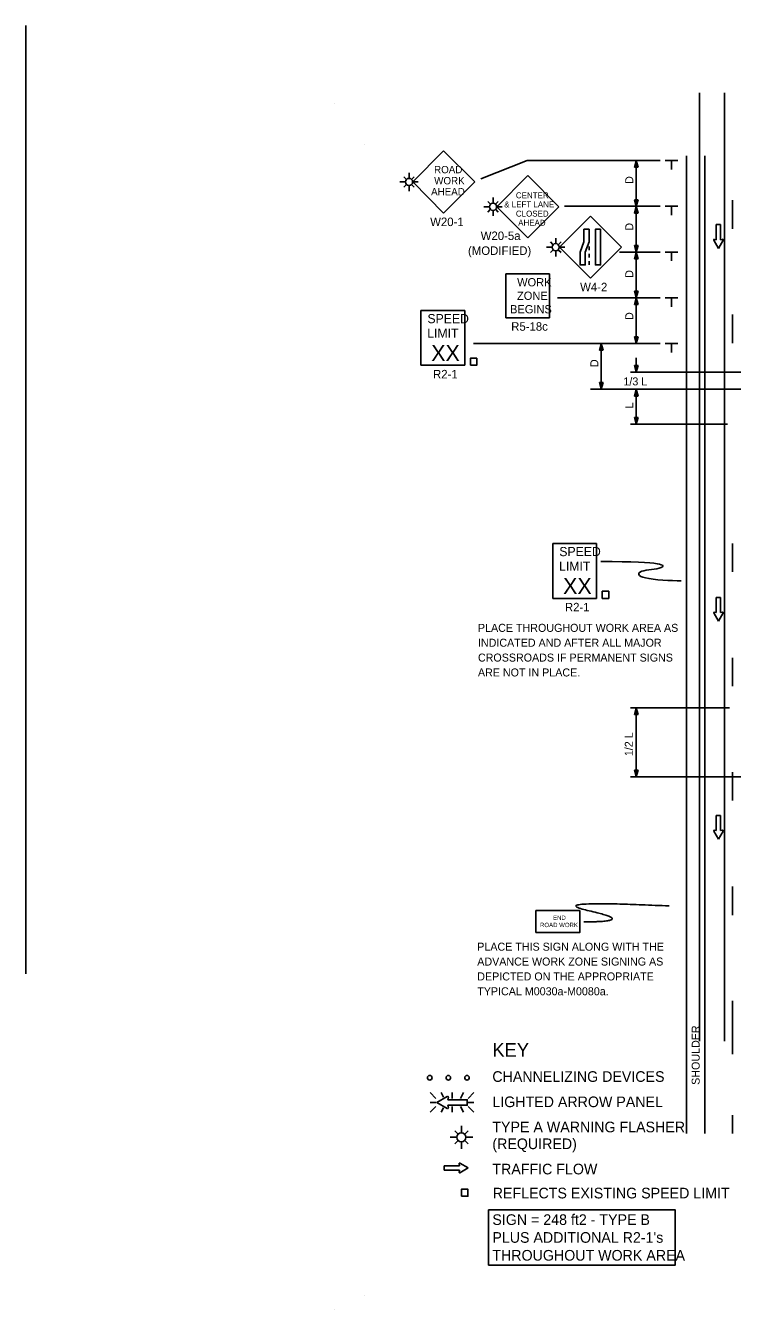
# Model space of a CAD drawing. Extents: x 16399 to 18476, y 7023 to 8321.
# Drawn here: x 16399 to 17017, y 7199 to 8321 of the extents above; entities that cross this region are included whole.
import ezdxf

# ---------------------------------------------------------------- set-up
doc = ezdxf.new("R2010")
doc.units = 0
for name, color, linetype in [('ALI_LEGAL_EX', 7, 'Continuous'), ('BORDER', 7, 'Continuous'), ('MT_SCRATCH_LEVEL_E', 7, 'Continuous'), ('PAVT_EDGE_EX', 7, 'Continuous'), ('TRAFFIC_SIGNS_PR', 7, 'Continuous'), ('TYPICAL_TEXT_DIMEN_EX', 7, 'Continuous'), ('TYPICAL_TEXT_DIMEN_PR', 7, 'Continuous')]:
    doc.layers.add(name, color=color, linetype=linetype)

msp = doc.modelspace()

# ---------------------------------------------------------------- linework, layer by layer
at = {"layer": 'ALI_LEGAL_EX'}
for points in [[(17017.1, 8168.5), (17017.1, 8143.5)], [(17017.1, 8068.5), (17017.1, 8043.5)], [(17017.1, 7868.5), (17017.1, 7843.5)], [(17017.1, 7768.5), (17017.1, 7743.5)], [(17017.1, 7668.5), (17017.1, 7643.5)], [(17017.1, 7568.5), (17017.1, 7543.5)], [(17017.1, 7468.5), (17017.1, 7443.5)], [(17017.1, 7368.5), (17017.1, 7352.5)]]:
    msp.add_lwpolyline(points, dxfattribs=at)
at = {"layer": 'BORDER'}
for p, q in [((16669.3, 8252.7), (16669.3, 8252.7)), ((16695.5, 8217), (16695.5, 8217)), ((16695.5, 7210.7), (16695.5, 7210.7)), ((16669.3, 7198.7), (16669.3, 7198.7))]:
    msp.add_line(p, q, dxfattribs=at)
at = {"layer": 'MT_SCRATCH_LEVEL_E'}
for p, q in [((17006.8, 8147.3), (17003, 8147.3)), ((17003, 8147.3), (17003, 8134)), ((17006.8, 8147.3), (17003, 8147.3)), ((17003, 8147.3), (17003, 8134)), ((17006.8, 8134), (17006.8, 8147.3)), ((17006.8, 8134), (17006.8, 8147.3)), ((17000.8, 8133.6), (17004.9, 8126.4)), ((17000.8, 8133.6), (17004.9, 8126.4)), ((17003, 8134), (17001.2, 8134.3)), ((17003, 8134), (17001.2, 8134.3)), ((17004.9, 8126.4), (17009, 8133.6)), ((17004.9, 8126.4), (17009, 8133.6)), ((17008.5, 8134.3), (17006.8, 8134)), ((17008.5, 8134.3), (17006.8, 8134)), ((17006.8, 7821.2), (17003, 7821.2)), ((17003, 7821.2), (17003, 7807.9)), ((17006.8, 7821.2), (17003, 7821.2)), ((17003, 7821.2), (17003, 7807.9)), ((17006.8, 7807.9), (17006.8, 7821.2)), ((17006.8, 7807.9), (17006.8, 7821.2)), ((17000.8, 7807.6), (17004.9, 7800.3)), ((17000.8, 7807.6), (17004.9, 7800.3)), ((17003, 7807.9), (17001.2, 7808.2)), ((17003, 7807.9), (17001.2, 7808.2)), ((17004.9, 7800.3), (17009, 7807.6)), ((17004.9, 7800.3), (17009, 7807.6)), ((17008.5, 7808.2), (17006.8, 7807.9)), ((17008.5, 7808.2), (17006.8, 7807.9)), ((17006.8, 7630.6), (17003, 7630.6)), ((17003, 7630.6), (17003, 7617.3)), ((17006.8, 7630.6), (17003, 7630.6)), ((17003, 7630.6), (17003, 7617.3)), ((17006.8, 7617.3), (17006.8, 7630.6)), ((17006.8, 7617.3), (17006.8, 7630.6)), ((17000.8, 7616.9), (17004.9, 7609.7)), ((17000.8, 7616.9), (17004.9, 7609.7)), ((17003, 7617.3), (17001.2, 7617.6)), ((17003, 7617.3), (17001.2, 7617.6)), ((17004.9, 7609.7), (17009, 7616.9)), ((17004.9, 7609.7), (17009, 7616.9)), ((17008.5, 7617.6), (17006.8, 7617.3)), ((17008.5, 7617.6), (17006.8, 7617.3)), ((16778.3, 7324.2), (16765, 7324.2)), ((16765, 7324.2), (16765, 7320.5)), ((16778.3, 7324.2), (16765, 7324.2)), ((16765, 7324.2), (16765, 7320.5)), ((16765, 7320.5), (16778.3, 7320.5)), ((16765, 7320.5), (16778.3, 7320.5)), ((16778, 7326), (16778.3, 7324.2)), ((16778, 7326), (16778.3, 7324.2)), ((16778.3, 7320.5), (16778, 7318.7)), ((16778.3, 7320.5), (16778, 7318.7)), ((16785.9, 7322.4), (16778.6, 7326.5)), ((16785.9, 7322.4), (16778.6, 7326.5)), ((16778.6, 7318.2), (16785.9, 7322.4)), ((16778.6, 7318.2), (16785.9, 7322.4))]:
    msp.add_line(p, q, dxfattribs=at)
for centre, start, end in [((17001.2, 8133.9), 80.0362, 209.7731), ((17001.2, 8133.9), 80.0362, 209.7731), ((17008.6, 8133.9), 330.4248, 99.9638), ((17008.6, 8133.9), 330.4248, 99.9638), ((17001.2, 7807.8), 80.0362, 209.7731), ((17001.2, 7807.8), 80.0362, 209.7731), ((17008.6, 7807.8), 330.4248, 99.9638), ((17008.6, 7807.8), 330.4248, 99.9638), ((17001.2, 7617.2), 80.0362, 209.7731), ((17001.2, 7617.2), 80.0362, 209.7731), ((17008.6, 7617.2), 330.4248, 99.9638), ((17008.6, 7617.2), 330.4248, 99.9638), ((16778.4, 7326.1), 60.4248, 189.9638), ((16778.4, 7326.1), 60.4248, 189.9638), ((16778.4, 7318.6), 170.0362, 299.7731), ((16778.4, 7318.6), 170.0362, 299.7731)]:
    msp.add_arc(centre, 0.463, start, end, dxfattribs=at)
at = {"layer": 'PAVT_EDGE_EX'}
for p, q in [((16398.8, 8321.2), (16398.8, 7492)), ((16988.2, 8262.3), (16988.2, 7433.2)), ((17010.2, 8262.3), (17010.2, 7433.2)), ((16977.1, 8207.3), (16977.1, 7352.5)), ((16993.1, 8207.3), (16993.1, 7352.5))]:
    msp.add_line(p, q, dxfattribs=at)
msp.add_lwpolyline([(17017.1, 7421.9), (17017.1, 7446.9)], dxfattribs=at)
at = {"layer": 'TRAFFIC_SIGNS_PR'}
for p, q in [((16764.5, 8211.7), (16737.4, 8184.5)), ((16791.7, 8184.5), (16764.5, 8211.7)), ((16731.1, 8184.5), (16726.2, 8184.5)), ((16731.7, 8187), (16729.6, 8189.1)), ((16734.2, 8188.1), (16734.2, 8192.6)), ((16736.7, 8187), (16738.8, 8189.1)), ((16737.4, 8184.5), (16764.5, 8157.3)), ((16737.4, 8184.5), (16742.2, 8184.5)), ((16764.5, 8157.3), (16791.7, 8184.5)), ((16838, 8190), (16810.9, 8162.8)), ((16865.2, 8162.8), (16838, 8190)), ((16731.7, 8182), (16729.6, 8179.9)), ((16734.2, 8176.5), (16734.2, 8181)), ((16736.7, 8182), (16738.8, 8179.9)), ((16804.5, 8162.8), (16799.7, 8162.8)), ((16805.2, 8165.3), (16803.1, 8167.4)), ((16805.2, 8160.3), (16803.1, 8158.2)), ((16807.7, 8166.4), (16807.7, 8170.9)), ((16810.2, 8165.3), (16812.3, 8167.4)), ((16810.2, 8160.3), (16812.3, 8158.2)), ((16810.9, 8162.8), (16815.7, 8162.8)), ((16810.9, 8162.8), (16838, 8135.6)), ((16838, 8135.6), (16865.2, 8162.8)), ((16807.7, 8154.9), (16807.7, 8159.3)), ((16892.9, 8154.6), (16865.8, 8127.5)), ((16920.1, 8127.5), (16892.9, 8154.6)), ((16859.4, 8127.4), (16854.6, 8127.4)), ((16860, 8129.9), (16857.9, 8132)), ((16862.5, 8130.9), (16862.5, 8135.4)), ((16865.1, 8129.9), (16867.2, 8132)), ((16865.7, 8127.4), (16870.6, 8127.4)), ((16865.8, 8127.5), (16892.9, 8100.3)), ((16891.7, 8128), (16891.7, 8124.8)), ((16892.9, 8100.3), (16920.1, 8127.5)), ((16860, 8124.8), (16857.9, 8122.7)), ((16862.5, 8119.4), (16862.5, 8123.8)), ((16865.1, 8124.8), (16867.2, 8122.7)), ((16891.7, 8121.6), (16891.7, 8118.4)), ((16818.8, 8065.8), (16818.8, 8104.2)), ((16818.8, 8104.2), (16857.2, 8104.2)), ((16857.2, 8065.8), (16857.2, 8104.2)), ((16891.7, 8115.2), (16891.7, 8112)), ((16744.5, 8072.2), (16782.9, 8072.2)), ((16744.5, 8024.2), (16744.5, 8072.2)), ((16782.9, 8024.2), (16782.9, 8072.2)), ((16818.8, 8065.8), (16857.2, 8065.8)), ((16744.5, 8024.2), (16782.9, 8024.2)), ((16859.9, 7868.4), (16898.3, 7868.4)), ((16859.9, 7820.4), (16859.9, 7868.4)), ((16898.3, 7820.4), (16898.3, 7868.4)), ((16859.9, 7820.4), (16898.3, 7820.4)), ((16752.7, 7388.2), (16757.7, 7383.2)), ((16764.5, 7384.3), (16762.3, 7388.2)), ((16771.8, 7383.2), (16771.8, 7388.2)), ((16779.1, 7383.2), (16781.9, 7388.2)), ((16786, 7383.2), (16790.9, 7388.2)), ((16757.7, 7379.7), (16752.7, 7379.7)), ((16752.7, 7371.2), (16757.7, 7376.1)), ((16762.2, 7371.2), (16764.4, 7374.8)), ((16771.8, 7376.1), (16771.8, 7371.2)), ((16781.9, 7371.2), (16779.1, 7376.1)), ((16786, 7379.7), (16790.9, 7379.7)), ((16786, 7376.1), (16790.9, 7371.2)), ((16776.9, 7352.2), (16774.3, 7354.9)), ((16780, 7353.5), (16780, 7359.1)), ((16783.2, 7352.2), (16785.8, 7354.9)), ((16776.1, 7349.1), (16770.1, 7349.1)), ((16776.9, 7345.9), (16774.3, 7343.3)), ((16780, 7339.1), (16780, 7344.6)), ((16783.2, 7345.9), (16785.8, 7343.3)), ((16784, 7349.1), (16790.1, 7349.1))]:
    msp.add_line(p, q, dxfattribs=at)
for points in [[(16891.7, 8143.2), (16891.7, 8132), (16888.4, 8123.1), (16888.4, 8112), (16883.9, 8112), (16883.9, 8123.1), (16887.2, 8132), (16887.2, 8143.2)], [(16901.8, 8143.2), (16901.8, 8112), (16897.3, 8112), (16897.3, 8143.2)], [(16787.9, 8024.2), (16793.5, 8024.2), (16793.5, 8030.3), (16787.9, 8030.3)], [(16903.3, 7820.4), (16908.9, 7820.4), (16908.9, 7826.6), (16903.3, 7826.6)], [(16845.2, 7528.1), (16883.6, 7528.1), (16883.6, 7547.3), (16845.2, 7547.3)], [(16780.1, 7297.6), (16785.7, 7297.6), (16785.7, 7303.7), (16780.1, 7303.7)]]:
    msp.add_lwpolyline(points, close=True, dxfattribs=at)
for points in [[(16767.7, 7384.9), (16758.5, 7379.7), (16767.7, 7374.3)], [(16768.6, 7375), (16768.2, 7377.2), (16785.2, 7377.2), (16785.2, 7382), (16768.2, 7382), (16768.6, 7384.3)]]:
    msp.add_lwpolyline(points, dxfattribs=at)
for centre, radius in [((16734.2, 8184.5), 3.15), ((16807.7, 8162.8), 3.15), ((16862.5, 8127.4), 3.15), ((16752.3, 7401.2), 2), ((16768.6, 7401.2), 2), ((16784.9, 7401.2), 2), ((16780, 7349.1), 3.94)]:
    msp.add_circle(centre, radius, dxfattribs=at)
for centre, radius, start, end in [((16768, 7384.4), 0.598, 350.7308, 118.8916), ((16768, 7374.9), 0.597, 241.4833, 9.9593)]:
    msp.add_arc(centre, radius, start, end, dxfattribs=at)
msp.add_open_spline([(16887.2, 7537.5), (16934.4, 7537.5), (16849.4, 7556.8), (16961.7, 7551.4)], degree=2, dxfattribs=at)
at = {"layer": 'TYPICAL_TEXT_DIMEN_EX'}
msp.add_lwpolyline([(16803.8, 7285.6), (16967.1, 7285.6), (16967.1, 7237.4), (16803.8, 7237.4)], close=True, dxfattribs=at)
at = {"layer": 'TYPICAL_TEXT_DIMEN_PR'}
for p, q in [((16797, 8187.1), (16837.7, 8203.2)), ((16837.7, 8203.2), (16954, 8203.2)), ((16877.1, 8203.2), (16954, 8203.2)), ((16931.4, 8197.3), (16933, 8203.2)), ((16933, 8197.3), (16931.4, 8197.3)), ((16933, 8163.2), (16933, 8203.2)), ((16933, 8203.2), (16934.6, 8197.3)), ((16934.6, 8197.3), (16933, 8197.3)), ((16958.2, 8203.2), (16969.5, 8203.2)), ((16963.9, 8203.2), (16963.9, 8195.4)), ((16870.3, 8163.2), (16954, 8163.2)), ((16933, 8163.2), (16931.4, 8169)), ((16931.4, 8169), (16933, 8169)), ((16931.4, 8157.3), (16933, 8163.2)), ((16933, 8169), (16934.6, 8169)), ((16934.6, 8169), (16933, 8163.2)), ((16933, 8163.2), (16934.6, 8157.3)), ((16933, 8123.2), (16933, 8163.2)), ((16958.2, 8163.2), (16969.5, 8163.2)), ((16963.9, 8163.2), (16963.9, 8155.4)), ((16933, 8157.3), (16931.4, 8157.3)), ((16934.6, 8157.3), (16933, 8157.3)), ((16933, 8123.2), (16931.4, 8129)), ((16931.4, 8129), (16933, 8129)), ((16933, 8129), (16934.6, 8129)), ((16934.6, 8129), (16933, 8123.2)), ((16918.3, 8123.2), (16954, 8123.2)), ((16931.4, 8117.3), (16933, 8123.2)), ((16933, 8117.3), (16931.4, 8117.3)), ((16933, 8083.2), (16933, 8123.2)), ((16933, 8123.2), (16934.6, 8117.3)), ((16934.6, 8117.3), (16933, 8117.3)), ((16958.2, 8123.2), (16969.5, 8123.2)), ((16963.9, 8123.2), (16963.9, 8115.4)), ((16864, 8083.2), (16954, 8083.2)), ((16933, 8083.2), (16931.4, 8089)), ((16931.4, 8089), (16933, 8089)), ((16931.4, 8077.3), (16933, 8083.2)), ((16933, 8089), (16934.6, 8089)), ((16934.6, 8089), (16933, 8083.2)), ((16933, 8043.2), (16933, 8083.2)), ((16933, 8083.2), (16934.6, 8077.3)), ((16958.2, 8083.2), (16969.5, 8083.2)), ((16963.9, 8083.2), (16963.9, 8075.4)), ((16933, 8077.3), (16931.4, 8077.3)), ((16934.6, 8077.3), (16933, 8077.3)), ((16933, 8043.2), (16931.4, 8049)), ((16931.4, 8049), (16933, 8049)), ((16933, 8049), (16934.6, 8049)), ((16934.6, 8049), (16933, 8043.2)), ((16790.7, 8043.2), (16954, 8043.2)), ((16900.8, 8037.3), (16902.4, 8043.2)), ((16902.4, 8037.3), (16900.8, 8037.3)), ((16902.4, 8043.2), (16904, 8037.3)), ((16902.4, 8003.2), (16902.4, 8043.2)), ((16904, 8037.3), (16902.4, 8037.3)), ((16958.2, 8043.2), (16969.5, 8043.2)), ((16963.9, 8043.2), (16963.9, 8035.4)), ((16933, 8030.6), (16933, 8018.1)), ((16928, 8018.1), (17057.1, 8018.1)), ((16933, 8018.1), (16931.4, 8024)), ((16931.4, 8024), (16933, 8024)), ((16933, 8024), (16934.6, 8024)), ((16934.6, 8024), (16933, 8018.1)), ((17033.9, 8003.2), (16892.9, 8003.2)), ((16902.4, 8003.2), (16900.8, 8009)), ((16900.8, 8009), (16902.4, 8009)), ((16902.4, 8009), (16904, 8009)), ((16904, 8009), (16902.4, 8003.2)), ((17033.9, 8003.2), (16902.4, 8003.2)), ((16931.4, 7997.3), (16933, 8003.2)), ((16933, 7972.6), (16933, 8003.2)), ((16933, 8003.2), (16934.6, 7997.3)), ((16933, 7997.3), (16931.4, 7997.3)), ((16934.6, 7997.3), (16933, 7997.3)), ((16928, 7972.6), (17012.8, 7972.6)), ((16933, 7972.6), (16931.4, 7978.5)), ((16931.4, 7978.5), (16933, 7978.5)), ((16933, 7978.5), (16934.6, 7978.5)), ((16934.6, 7978.5), (16933, 7972.6)), ((16928, 7724.7), (17014.5, 7724.7)), ((16931.4, 7718.8), (16933, 7724.7)), ((16933, 7664.2), (16933, 7724.7)), ((16933, 7724.7), (16934.6, 7718.8)), ((16933, 7718.8), (16931.4, 7718.8)), ((16934.6, 7718.8), (16933, 7718.8)), ((16933, 7664.2), (16931.4, 7670.1)), ((16931.4, 7670.1), (16933, 7670.1)), ((16933, 7670.1), (16934.6, 7670.1)), ((16934.6, 7670.1), (16933, 7664.2)), ((16928, 7664.2), (17057.6, 7664.2))]:
    msp.add_line(p, q, dxfattribs=at)
msp.add_open_spline([(16901.9, 7852.5), (16959, 7852.7), (16958.9, 7845.5), (16933.8, 7845.5), (16933.8, 7837.1), (16963.4, 7835.9), (16972.3, 7835.7)], degree=3, dxfattribs=at)

# ---------------------------------------------------------------- texts
at = {"layer": 'TRAFFIC_SIGNS_PR'}
for s, height, p in [('ROAD', 6.41, (16756.1, 8192.1)), ('WORK', 6.41, (16756.2, 8182.4)), ('AHEAD', 6.41, (16753.5, 8172.8)), ('CENTER', 5.21, (16827.7, 8170.2)), ('CENTER', 5.21, (16827.7, 8170.2)), ('& LEFT LANE', 5.206, (16817.5, 8162.2)), ('& LEFT LANE', 5.206, (16817.5, 8162.2)), ('W20-1', 7.45, (16752.7, 8145.9)), ('CLOSED', 5.21, (16827.7, 8154.2)), ('CLOSED', 5.21, (16827.7, 8154.2)), ('AHEAD', 5.21, (16829.7, 8146.2)), ('AHEAD', 5.21, (16829.7, 8146.2)), ('W20-5a', 7.45, (16796.9, 8133.7)), ('(MODIFIED)', 7.45, (16785.8, 8120.7)), ('WORK', 7.22, (16828.8, 8093.2)), ('W4-2', 7.44, (16883.9, 8088.9)), ('ZONE', 7.22, (16828.7, 8081.4)), ('BEGINS', 7.22, (16822.6, 8069.6)), ('SPEED', 8, (16750.3, 8061)), ('R5-18c', 7.44, (16823.6, 8054.4)), ('LIMIT', 8, (16750.1, 8048.2)), ('XX', 14.03, (16753.6, 8027.9)), ('R2-1', 7.44, (16755.2, 8012.7)), ('SPEED', 8, (16865.7, 7857.3)), ('LIMIT', 8, (16865.5, 7844.5)), ('XX', 14.03, (16869, 7824.2)), ('R2-1', 7.44, (16870.6, 7809)), ('PLACE THROUGHOUT WORK AREA AS', 7, (16794.5, 7791.1)), ('INDICATED AND AFTER ALL MAJOR', 7, (16794.5, 7778.1)), ('CROSSROADS IF PERMANENT SIGNS', 7, (16794.5, 7765.1)), ('ARE NOT IN PLACE.', 7, (16794.5, 7752.1)), ('END', 3.83, (16860.2, 7539.2)), ('ROAD WORK', 3.83, (16848.8, 7532.9)), ('PLACE THIS SIGN ALONG WITH THE', 7, (16793.9, 7512.3)), ('ADVANCE WORK ZONE SIGNING AS', 7, (16793.9, 7499.3)), ('DEPICTED ON THE APPROPRIATE', 7, (16793.9, 7486.3)), ('TYPICAL M0030a-M0080a.', 7, (16793.9, 7473.3))]:
    msp.add_text(s, height=height, dxfattribs=at).set_placement(p)
at = {"layer": 'TYPICAL_TEXT_DIMEN_EX'}
for s, height, p in [('KEY', 12, (16807.1, 7419.6)), ('CHANNELIZING DEVICES', 9.3, (16807.1, 7397.6)), ('LIGHTED ARROW PANEL', 9.3, (16807.1, 7375.5)), ('TYPE A WARNING FLASHER', 9.3, (16807.1, 7353.5)), ('(REQUIRED)', 9.3, (16807.1, 7338.8)), ('TRAFFIC FLOW', 9.3, (16807.1, 7316.7)), ('REFLECTS EXISTING SPEED LIMIT', 9.3, (16807.4, 7295.7)), ('SIGN = 248 ft2 - TYPE B', 9.3, (16807.1, 7272.5)), ("PLUS ADDITIONAL R2-1's", 9.3, (16807.1, 7256.9)), ('THROUGHOUT WORK AREA', 9.3, (16807.1, 7241.3))]:
    msp.add_text(s, height=height, dxfattribs=at).set_placement(p)
at = {"layer": 'TYPICAL_TEXT_DIMEN_PR'}
for s, p in [('D', (16930.4, 8182.8)), ('D', (16930.4, 8141.9)), ('D', (16930.4, 8100.7)), ('D', (16930.4, 8063.8)), ('D', (16899.8, 8022.6)), ('L', (16930.4, 7986.5)), ('1/2 L', (16930, 7682.4)), ('SHOULDER', (16988.5, 7395))]:
    msp.add_text(s, height=7, rotation=90, dxfattribs=at).set_placement(p)
msp.add_text('1/3 L', height=7, dxfattribs=at).set_placement((16921.8, 8006.6))

doc.saveas('drawing.dxf')
